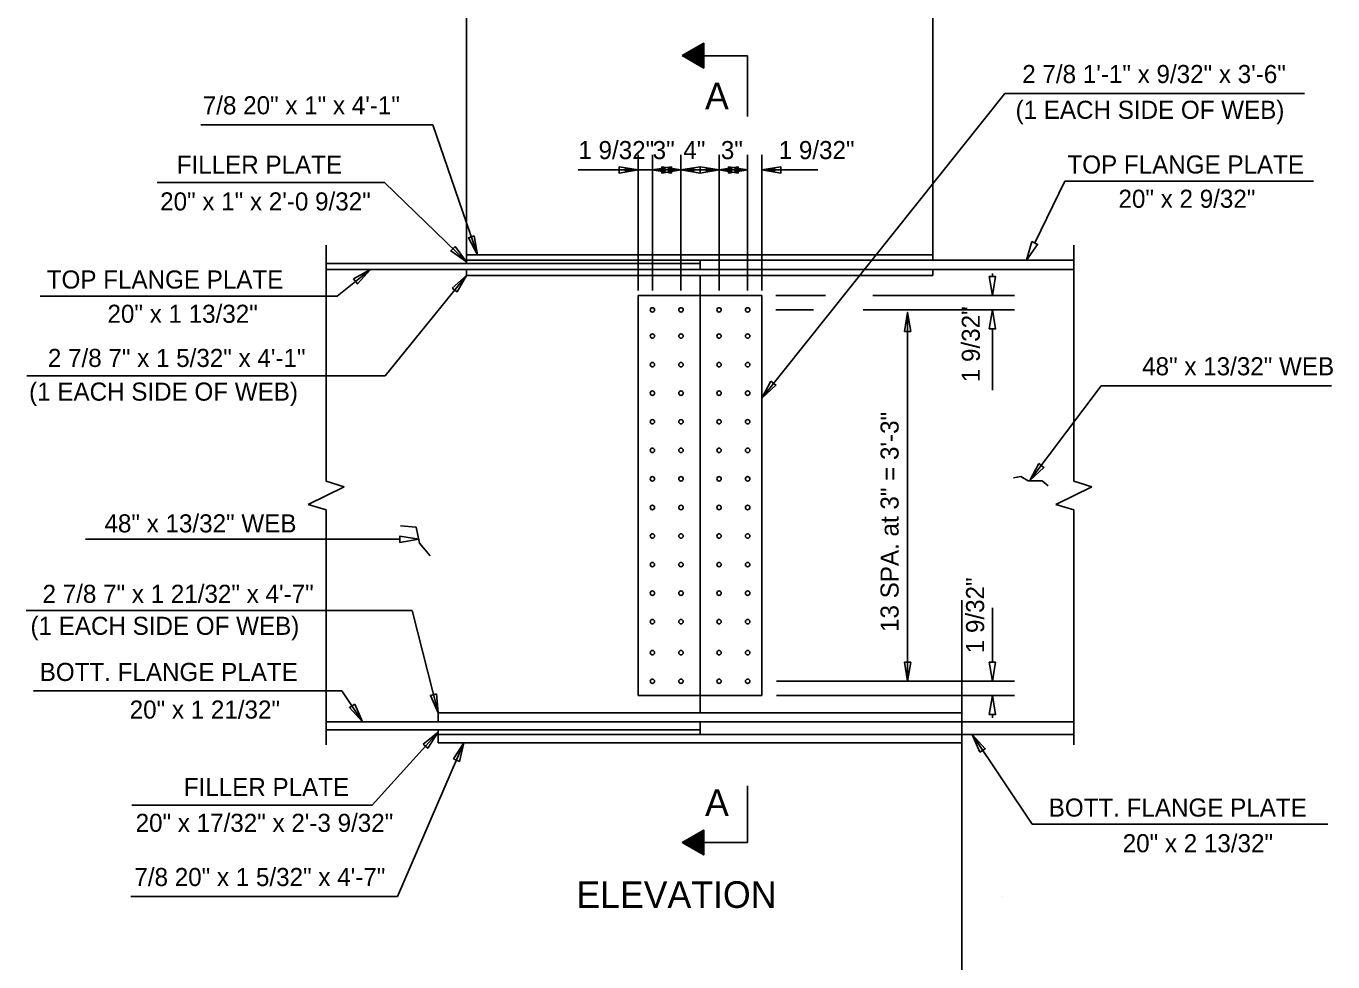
# Model space of a CAD drawing. Extents: x 4944 to 17449, y 3824 to 49087.
# Drawn here: x 13096 to 13928, y 33442 to 34038 of the extents above; entities that cross this region are included whole.
import ezdxf

# ---------------------------------------------------------------- set-up
doc = ezdxf.new("R2010")
doc.units = 0
for name, color, linetype in [('1', 7, 'Continuous'), ('2', 7, 'Continuous'), ('36_S_LINES', 7, 'Continuous'), ('3A', 7, 'Continuous'), ('4', 7, 'Continuous'), ('BEAM', 7, 'Continuous'), ('Level 25', 7, 'Continuous')]:
    doc.layers.add(name, color=color, linetype=linetype)

# ---------------------------------------------------------------- blocks, each defined once
blk = doc.blocks.new('SC1136')
at = {"layer": '1'}
for p, q in [((0.4549, 0.5156), (0.5451, 0.5156)), ((0.4571, 0.5195), (0.5429, 0.5195)), ((0.4594, 0.5234), (0.5406, 0.5234)), ((0.4617, 0.5273), (0.5383, 0.5273)), ((0.4639, 0.5312), (0.5361, 0.5312)), ((0.4662, 0.5352), (0.5338, 0.5352)), ((0.4684, 0.5391), (0.5316, 0.5391)), ((0.4707, 0.543), (0.5293, 0.543)), ((0.4729, 0.5469), (0.5271, 0.5469)), ((0.4752, 0.5508), (0.5248, 0.5508)), ((0.4774, 0.5547), (0.5226, 0.5547)), ((0.4797, 0.5586), (0.5203, 0.5586)), ((0.482, 0.5625), (0.518, 0.5625)), ((0.4842, 0.5664), (0.5158, 0.5664)), ((0.4865, 0.5703), (0.5135, 0.5703)), ((0.4887, 0.5742), (0.5113, 0.5742)), ((0.491, 0.5781), (0.509, 0.5781)), ((0.4932, 0.582), (0.5068, 0.582)), ((0.4955, 0.5859), (0.5045, 0.5859)), ((0.4977, 0.5898), (0.5023, 0.5898)), ((0.4188, 0.4531), (0.5812, 0.4531)), ((0.4211, 0.457), (0.5789, 0.457)), ((0.4233, 0.4609), (0.5767, 0.4609)), ((0.4256, 0.4648), (0.5744, 0.4648)), ((0.4278, 0.4688), (0.5722, 0.4688)), ((0.4301, 0.4727), (0.5699, 0.4727)), ((0.4323, 0.4766), (0.5677, 0.4766)), ((0.4346, 0.4805), (0.5654, 0.4805)), ((0.4369, 0.4844), (0.5631, 0.4844)), ((0.4391, 0.4883), (0.5609, 0.4883)), ((0.4414, 0.4922), (0.5586, 0.4922)), ((0.4436, 0.4961), (0.5564, 0.4961)), ((0.4459, 0.5), (0.5541, 0.5)), ((0.4481, 0.5039), (0.5519, 0.5039)), ((0.4504, 0.5078), (0.5496, 0.5078)), ((0.4526, 0.5117), (0.5474, 0.5117))]:
    blk.add_line(p, q, dxfattribs=at)
blk = doc.blocks.new('DWG070')
at = {"layer": '1'}
blk.add_lwpolyline([(0, 0), (0.1406, -0.0812), (0.1406, 0.0812)], close=True, dxfattribs=at)
at = {"layer": '1', "rotation": 90}
blk.add_blockref('SC1136', (0.5945, -0.5), dxfattribs=at)
blk = doc.blocks.new('ARROWH')
at = {"layer": '1'}
blk.add_lwpolyline([(0.1231, -0.0212), (0.1231, 0.0205), (-0.0019, -0.0003)], close=True, dxfattribs=at)

msp = doc.modelspace()

# ---------------------------------------------------------------- linework, layer by layer
at = {"layer": '1'}
for centre, start, end in [((13494.7, 33857.28), 0, 180), ((13494.7, 33857.28), 180, 0), ((13512.89, 33857.28), 0, 180), ((13512.89, 33857.28), 180, 0), ((13537.15, 33857.28), 0, 180), ((13537.15, 33857.28), 180, 0), ((13555.34, 33857.28), 0, 180), ((13555.34, 33857.28), 180, 0), ((13494.7, 33840.62), 0, 180), ((13494.7, 33840.62), 180, 0), ((13512.89, 33840.62), 0, 180), ((13512.89, 33840.62), 180, 0), ((13537.15, 33840.62), 0, 180), ((13537.15, 33840.62), 180, 0), ((13555.34, 33840.62), 0, 180), ((13555.34, 33840.62), 180, 0), ((13494.7, 33822.43), 0, 180), ((13494.7, 33822.43), 180, 0), ((13512.89, 33822.43), 0, 180), ((13512.89, 33822.43), 180, 0), ((13537.15, 33822.43), 0, 180), ((13537.15, 33822.43), 180, 0), ((13555.34, 33822.43), 0, 180), ((13555.34, 33822.43), 180, 0), ((13494.7, 33804.24), 0, 180), ((13494.7, 33804.24), 180, 0), ((13512.89, 33804.24), 0, 180), ((13512.89, 33804.24), 180, 0), ((13537.15, 33804.24), 0, 180), ((13537.15, 33804.24), 180, 0), ((13555.34, 33804.24), 0, 180), ((13555.34, 33804.24), 180, 0), ((13494.7, 33786.05), 0, 180), ((13494.7, 33786.05), 180, 0), ((13512.89, 33786.05), 0, 180), ((13512.89, 33786.05), 180, 0), ((13537.15, 33786.05), 0, 180), ((13537.15, 33786.05), 180, 0), ((13555.34, 33786.05), 0, 180), ((13555.34, 33786.05), 180, 0), ((13494.7, 33767.85), 0, 180), ((13494.7, 33767.85), 180, 0), ((13512.89, 33767.85), 0, 180), ((13512.89, 33767.85), 180, 0), ((13537.15, 33767.85), 0, 180), ((13537.15, 33767.85), 180, 0), ((13555.34, 33767.85), 0, 180), ((13555.34, 33767.85), 180, 0), ((13494.7, 33749.66), 0, 180), ((13512.89, 33749.66), 0, 180), ((13537.15, 33749.66), 0, 180), ((13555.34, 33749.66), 0, 180), ((13494.7, 33749.66), 180, 0), ((13512.89, 33749.66), 180, 0), ((13537.15, 33749.66), 180, 0), ((13555.34, 33749.66), 180, 0), ((13494.7, 33731.47), 0, 180), ((13494.7, 33731.47), 180, 0), ((13512.89, 33731.47), 0, 180), ((13512.89, 33731.47), 180, 0), ((13537.15, 33731.47), 0, 180), ((13537.15, 33731.47), 180, 0), ((13555.34, 33731.47), 0, 180), ((13555.34, 33731.47), 180, 0), ((13494.7, 33713.28), 0, 180), ((13494.7, 33713.28), 180, 0), ((13512.89, 33713.28), 0, 180), ((13512.89, 33713.28), 180, 0), ((13537.15, 33713.28), 0, 180), ((13537.15, 33713.28), 180, 0), ((13555.34, 33713.28), 0, 180), ((13555.34, 33713.28), 180, 0), ((13494.7, 33695.08), 0, 180), ((13494.7, 33695.08), 180, 0), ((13512.89, 33695.08), 0, 180), ((13512.89, 33695.08), 180, 0), ((13537.15, 33695.08), 0, 180), ((13537.15, 33695.08), 180, 0), ((13555.34, 33695.08), 0, 180), ((13555.34, 33695.08), 180, 0), ((13494.7, 33676.89), 0, 180), ((13494.7, 33676.89), 180, 0), ((13512.89, 33676.89), 0, 180), ((13512.89, 33676.89), 180, 0), ((13537.15, 33676.89), 0, 180), ((13537.15, 33676.89), 180, 0), ((13555.34, 33676.89), 0, 180), ((13555.34, 33676.89), 180, 0), ((13494.7, 33658.7), 0, 180), ((13512.89, 33658.7), 0, 180), ((13537.15, 33658.7), 0, 180), ((13555.34, 33658.7), 0, 180), ((13494.7, 33658.7), 180, 0), ((13512.89, 33658.7), 180, 0), ((13537.15, 33658.7), 180, 0), ((13555.34, 33658.7), 180, 0), ((13494.7, 33638.96), 0, 180), ((13494.7, 33638.96), 180, 0), ((13512.89, 33638.96), 0, 180), ((13512.89, 33638.96), 180, 0), ((13537.15, 33638.96), 0, 180), ((13537.15, 33638.96), 180, 0), ((13555.34, 33638.96), 0, 180), ((13555.34, 33638.96), 180, 0), ((13494.7, 33620.77), 0, 180), ((13494.7, 33620.77), 180, 0), ((13512.89, 33620.77), 0, 180), ((13512.89, 33620.77), 180, 0), ((13537.15, 33620.77), 0, 180), ((13537.15, 33620.77), 180, 0), ((13555.34, 33620.77), 0, 180), ((13555.34, 33620.77), 180, 0)]:
    msp.add_arc(centre, 1.42, start, end, dxfattribs=at)
at = {"layer": '2'}
msp.add_line((13525.02, 33611.67), (13525.02, 33866.37), dxfattribs=at)
at = {"layer": '36_S_LINES'}
for p, q in [((13564.44, 33801.02), (13719.13, 33995.04)), ((13719.13, 33995.04), (13909.89, 33995.04)), ((13354.96, 33975.22), (13207.24, 33975.22)), ((13383.26, 33892.4), (13354.96, 33975.22)), ((13485.6, 33869.62), (13485.6, 33956.02)), ((13564.44, 33869.62), (13564.44, 33956.02)), ((13485.6, 33946.39), (13447.42, 33946.39)), ((13476.5, 33946.39), (13494.7, 33946.39)), ((13494.7, 33946.39), (13537.15, 33946.39)), ((13494.7, 33946.39), (13518.95, 33946.39)), ((13512.89, 33946.39), (13537.15, 33946.39)), ((13512.89, 33946.39), (13555.34, 33946.39)), ((13537.15, 33946.39), (13537.15, 33946.39)), ((13555.34, 33946.39), (13537.15, 33946.39)), ((13564.44, 33946.39), (13600.06, 33946.39)), ((13324.16, 33938.51), (13179.31, 33938.51)), ((13376.32, 33887.9), (13324.16, 33938.51)), ((13738.17, 33899.92), (13757.32, 33939.27)), ((13757.32, 33939.27), (13915.69, 33939.27)), ((13286.95, 33898.52), (13286.95, 33748.11)), ((13763.08, 33898.52), (13763.08, 33748.11)), ((13315.09, 33883.02), (13293.97, 33866.02)), ((13376.32, 33879.27), (13324.44, 33815.21)), ((13711.19, 33878.5), (13711.19, 33880.44)), ((13104.87, 33866.02), (13293.97, 33866.02)), ((13573.23, 33866.37), (13604.87, 33866.37)), ((13635.16, 33866.37), (13725.23, 33866.37)), ((13657.17, 33855.73), (13657.17, 33622.31)), ((13711.19, 33845.15), (13711.19, 33806.09)), ((13324.44, 33815.21), (13096.37, 33815.21)), ((13735.03, 33748.54), (13780.49, 33808.92)), ((13780.49, 33808.92), (13927.05, 33808.92)), ((13724.72, 33750.34), (13729.33, 33751.2)), ((13729.33, 33751.2), (13733.89, 33748.42)), ((13298.47, 33744.7), (13275.43, 33733.34)), ((13286.95, 33748.11), (13298.47, 33744.7)), ((13733.89, 33748.42), (13738.4, 33748.42)), ((13738.4, 33748.42), (13742.96, 33748.37)), ((13742.96, 33748.37), (13746.8, 33745.25)), ((13774.61, 33744.7), (13751.56, 33733.34)), ((13763.08, 33748.11), (13774.61, 33744.7)), ((13275.43, 33733.34), (13286.95, 33729.94)), ((13286.95, 33729.94), (13286.95, 33580.31)), ((13751.56, 33733.34), (13763.08, 33729.94)), ((13763.08, 33729.94), (13763.08, 33580.31)), ((13334.3, 33719.73), (13344.3, 33718.84)), ((13344.3, 33718.84), (13346.3, 33708.62)), ((13333.91, 33711.18), (13133.65, 33711.18)), ((13346.3, 33708.62), (13353.2, 33700.62)), ((13341.78, 33665.78), (13095.89, 33665.78)), ((13358.25, 33600.65), (13341.78, 33665.78)), ((13711.19, 33632.9), (13711.19, 33667.45)), ((13296.93, 33614.65), (13100.55, 33614.65)), ((13310.14, 33595.02), (13296.93, 33614.65)), ((13573.77, 33611.67), (13725.23, 33611.67)), ((13711.19, 33599.55), (13711.19, 33597.52)), ((13358.25, 33588.3), (13316.24, 33541.89)), ((13698.25, 33586.77), (13736.57, 33529.84)), ((13374.72, 33581.58), (13332.31, 33483.72)), ((13316.24, 33541.89), (13163.17, 33541.83)), ((13736.57, 33529.84), (13924.86, 33529.84)), ((13332.31, 33483.72), (13162.58, 33483.72))]:
    msp.add_line(p, q, dxfattribs=at)
for points in [[(13473.47, 33948.41), (13473.47, 33944.37), (13485.6, 33946.39)], [(13477.62, 33945.38), (13477.62, 33947.4), (13485.6, 33946.39)], [(13506.83, 33948.41), (13506.83, 33944.37), (13494.7, 33946.39)], [(13502.68, 33945.38), (13502.68, 33947.4), (13494.7, 33946.39)], [(13502.69, 33945.38), (13502.69, 33947.4), (13494.7, 33946.39)], [(13502.69, 33947.4), (13502.69, 33945.38), (13494.7, 33946.39)], [(13500.76, 33948.41), (13500.76, 33944.37), (13512.89, 33946.39)], [(13504.89, 33945.38), (13504.89, 33947.4), (13512.89, 33946.39)], [(13504.89, 33947.4), (13504.89, 33945.38), (13512.89, 33946.39)], [(13504.91, 33945.38), (13504.91, 33947.4), (13512.89, 33946.39)], [(13525.02, 33948.41), (13525.02, 33944.37), (13512.89, 33946.39)], [(13520.87, 33945.38), (13520.87, 33947.4), (13512.89, 33946.39)], [(13520.89, 33945.38), (13520.89, 33947.4), (13512.89, 33946.39)], [(13520.89, 33947.4), (13520.89, 33945.38), (13512.89, 33946.39)], [(13525.02, 33948.41), (13525.02, 33944.37), (13537.15, 33946.39)], [(13529.15, 33945.38), (13529.15, 33947.4), (13537.15, 33946.39)], [(13529.15, 33947.4), (13529.15, 33945.38), (13537.15, 33946.39)], [(13529.17, 33945.38), (13529.17, 33947.4), (13537.15, 33946.39)], [(13549.28, 33948.41), (13549.28, 33944.37), (13537.15, 33946.39)], [(13545.13, 33945.38), (13545.13, 33947.4), (13537.15, 33946.39)], [(13545.14, 33945.38), (13545.14, 33947.4), (13537.15, 33946.39)], [(13545.14, 33947.4), (13545.14, 33945.38), (13537.15, 33946.39)], [(13543.21, 33948.41), (13543.21, 33944.37), (13555.34, 33946.39)], [(13547.34, 33945.38), (13547.34, 33947.4), (13555.34, 33946.39)], [(13547.34, 33947.4), (13547.34, 33945.38), (13555.34, 33946.39)], [(13547.36, 33945.38), (13547.36, 33947.4), (13555.34, 33946.39)], [(13576.56, 33948.41), (13576.56, 33944.37), (13564.44, 33946.39)], [(13572.42, 33945.38), (13572.42, 33947.4), (13564.44, 33946.39)], [(13572.43, 33945.38), (13572.43, 33947.4), (13564.44, 33946.39)], [(13572.43, 33947.4), (13572.43, 33945.38), (13564.44, 33946.39)], [(13381.27, 33904.4), (13383.26, 33892.4), (13377.49, 33903.11)], [(13736.35, 33900.8), (13739.99, 33899.03), (13732.86, 33889.01)], [(13369.1, 33897.69), (13376.32, 33887.9), (13366.31, 33894.82)], [(13304.41, 33877.02), (13306.94, 33873.87), (13315.12, 33883.05)], [(13367.21, 33871.21), (13376.32, 33879.27), (13370.32, 33868.69)], [(13709.17, 33878.5), (13713.21, 33878.5), (13711.19, 33866.37)], [(13655.15, 33843.61), (13659.19, 33843.61), (13657.17, 33855.73)], [(13709.17, 33845.15), (13713.21, 33845.15), (13711.19, 33857.28)], [(13570.19, 33811.88), (13573.4, 33809.43), (13564.44, 33801.02)], [(13740.78, 33759.4), (13743.99, 33756.95), (13735.03, 33748.54)], [(13333.91, 33709.16), (13333.91, 33713.2), (13346.04, 33711.18)], [(13655.15, 33632.9), (13659.19, 33632.9), (13657.17, 33620.77)], [(13709.17, 33632.9), (13713.21, 33632.9), (13711.19, 33620.77)], [(13357.25, 33612.77), (13358.25, 33600.65), (13353.37, 33611.79)], [(13709.17, 33599.55), (13713.21, 33599.55), (13711.19, 33611.67)], [(13348.72, 33580.75), (13358.25, 33588.3), (13351.68, 33578.06)], [(13368.11, 33571.37), (13374.72, 33581.58), (13371.78, 33569.77)]]:
    msp.add_lwpolyline(points, close=True, dxfattribs=at)
at = {"layer": '3A'}
for p, q in [((13494.7, 33869.62), (13494.7, 33956.02)), ((13512.89, 33869.62), (13512.89, 33956.02)), ((13537.15, 33869.62), (13537.15, 33956.02)), ((13555.34, 33869.62), (13555.34, 33956.02)), ((13573.23, 33857.28), (13597.31, 33857.28)), ((13628.89, 33857.28), (13725.23, 33857.28)), ((13573.77, 33620.77), (13725.23, 33620.77))]:
    msp.add_line(p, q, dxfattribs=at)
at = {"layer": '4'}
for p, q in [((13513.73, 34018.99), (13555.17, 34018.99)), ((13555.17, 34018.99), (13555.17, 33980.4)), ((13555.17, 33518.06), (13555.17, 33554.18)), ((13513.73, 33518.06), (13555.17, 33518.06))]:
    msp.add_line(p, q, dxfattribs=at)
at = {"layer": 'DEFPOINTS'}
for p, q in [((13376.32, 34216.9), (13376.32, 33892.4)), ((13673.35, 34216.9), (13673.35, 33892.4)), ((13691.78, 33378.99), (13691.78, 33672.37)), ((13341.78, 33665.78), (13341.78, 33665.78)), ((13717.72, 33483.72), (13717.72, 33483.72))]:
    msp.add_line(p, q, dxfattribs=at)
at = {"layer": 'Level 25'}
for p, q in [((13525.02, 33886.77), (13286.95, 33886.77)), ((13673.35, 33892.4), (13376.32, 33892.4)), ((13376.32, 33889.02), (13376.32, 33892.4)), ((13763.08, 33889.02), (13376.32, 33889.02)), ((13376.32, 33889.02), (13376.32, 33886.77)), ((13525.02, 33883.02), (13525.02, 33889.02)), ((13673.35, 33889.02), (13673.35, 33892.4)), ((13763.08, 33883.02), (13286.95, 33883.02)), ((13376.32, 33879.27), (13376.32, 33883.02)), ((13673.35, 33879.27), (13376.32, 33879.27)), ((13525.02, 33866.37), (13525.02, 33879.27)), ((13673.35, 33879.27), (13673.35, 33883.02)), ((13485.6, 33866.37), (13564.44, 33866.37)), ((13485.6, 33611.67), (13485.6, 33866.37)), ((13564.44, 33611.67), (13564.44, 33866.37)), ((13485.6, 33611.67), (13564.44, 33611.67)), ((13525.02, 33600.59), (13525.02, 33611.67)), ((13763.08, 33595.02), (13286.95, 33595.02)), ((13358.25, 33595.08), (13358.25, 33600.65)), ((13691.67, 33600.65), (13358.25, 33600.65)), ((13525.02, 33586.77), (13525.02, 33595.02)), ((13691.67, 33595.08), (13691.67, 33600.65)), ((13525.02, 33589.77), (13286.95, 33589.77)), ((13358.25, 33586.83), (13358.25, 33589.77)), ((13358.25, 33581.58), (13358.25, 33586.83)), ((13763.08, 33586.77), (13358.25, 33586.83)), ((13691.67, 33581.54), (13691.67, 33586.83)), ((13691.67, 33581.54), (13358.25, 33581.58))]:
    msp.add_line(p, q, dxfattribs=at)

# ---------------------------------------------------------------- block references
at = {"layer": '36_S_LINES'}
for p, xscale, yscale, rotation in [((13310.01, 33595.16), 97.0280040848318, 97.02800408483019, 123.60584756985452), ((13698.38, 33586.64), 97.02800408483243, 97.02800408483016, -56.61183182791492)]:
    msp.add_blockref('ARROWH', p, dxfattribs=dict(at, xscale=xscale, yscale=yscale, rotation=rotation))
at = {"layer": '4', "xscale": 97.02800408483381}
for p, yscale in [((13513.72, 34019.21), 97.02800408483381), ((13513.72, 33518.06), -97.02800408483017)]:
    msp.add_blockref('DWG070', p, dxfattribs=dict(at, yscale=yscale))

# ---------------------------------------------------------------- texts
at = {"layer": '3A'}
for s, p in [('2 7/8 1\'-1" x 9/32" x 3\'-6"', (13730.22, 34001.75)), ('7/8 20" x 1" x 4\'-1"', (13208.39, 33981.84)), ('(1 EACH SIDE OF WEB)', (13725.95, 33978.97)), ('1 9/32"', (13447.55, 33953.31)), ('3"', (13494.86, 33953.31)), ('4"', (13514.38, 33953.31)), ('3"', (13538.28, 33953.31)), ('1 9/32"', (13575.14, 33953.31)), ('FILLER PLATE', (13191.77, 33944.03)), ('TOP FLANGE PLATE', (13759, 33944.13)), ('20" x 2 9/32"', (13791.5, 33922.31)), ('20" x 1" x 2\'-0 9/32"', (13181.24, 33920.62)), ('TOP FLANGE PLATE', (13109.02, 33870.88)), ('20" x 1 13/32"', (13147.69, 33849.06)), ('2 7/8 7" x 1 5/32" x 4\'-1"', (13109.75, 33820.94)), ('48" x 13/32" WEB', (13806.57, 33815.63)), ('(1 EACH SIDE OF WEB)', (13097.79, 33799.49)), ('48" x 13/32" WEB', (13145.78, 33715.57)), ('2 7/8 7" x 1 21/32" x 4\'-7"', (13106.35, 33670.71)), ('(1 EACH SIDE OF WEB)', (13098.66, 33650.33)), ('BOTT. FLANGE PLATE', (13104.53, 33620.96)), ('20" x 1 21/32"', (13161.83, 33596.99)), ('FILLER PLATE', (13196.28, 33547.6)), ('BOTT. FLANGE PLATE', (13747.05, 33534.57)), ('20" x 17/32" x 2\'-3 9/32"', (13165.61, 33524.85)), ('20" x 2 13/32"', (13794.18, 33511.87)), ('7/8 20" x 1 5/32" x 4\'-7"', (13164.83, 33490.34))]:
    msp.add_text(s, height=11.52, dxfattribs=at).set_placement(p)
for s, p in [('1 9/32"', (13703.2, 33811.26)), ('13 SPA. at 3" = 3\'-3"', (13651.48, 33652.17)), ('1 9/32"', (13705.94, 33638.63))]:
    msp.add_text(s, height=11.52, rotation=90, dxfattribs=at).set_placement(p)
at = {"layer": 'BEAM'}
for s, p in [('A', (13528.22, 33985.07)), ('A', (13528.22, 33535)), ('ELEVATION', (13446.24, 33476.43))]:
    msp.add_text(s, height=16.98, dxfattribs=at).set_placement(p)

doc.saveas('drawing.dxf')
